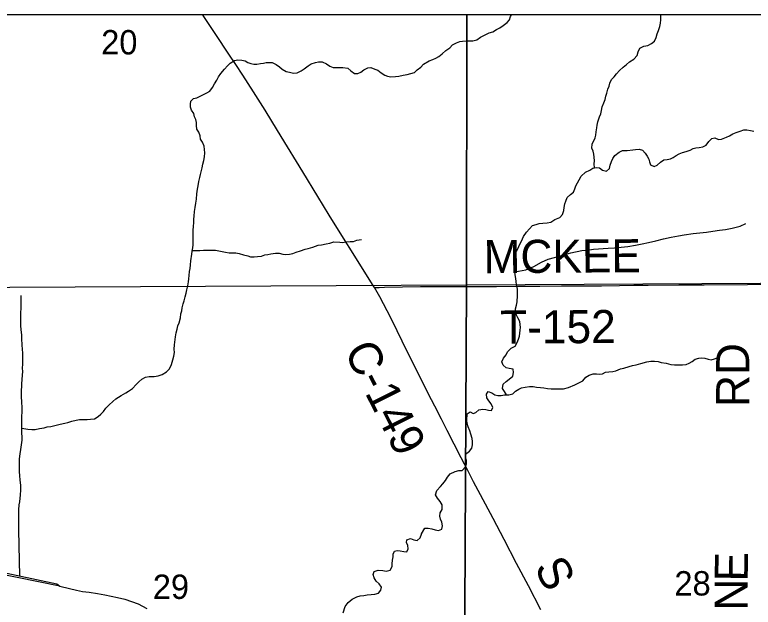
# Model space of a CAD drawing. Extents: x 0 to 34, y 0 to 22.
# Drawn here: x 4.701 to 5.97, y 19.882 to 20.9 of the extents above; entities that cross this region are included whole.
import ezdxf

# ---------------------------------------------------------------- set-up
doc = ezdxf.new("R2010")
doc.units = 0
for name, color, linetype in [('Default', 7, 'Continuous'), ('GM_X_County_Road', 7, 'Continuous'), ('GM_X_County_Road_Text', 7, 'Continuous'), ('GM_X_Minor_River', 7, 'Continuous'), ('GM_X_Section', 7, 'Continuous'), ('GM_X_Section_Text', 7, 'Continuous'), ('GM_X_Township_Road', 7, 'Continuous'), ('GM_X_Township_Road_Text', 7, 'Continuous'), ('SH_Cut_Line', 7, 'Continuous')]:
    doc.layers.add(name, color=color, linetype=linetype)

msp = doc.modelspace()

# ---------------------------------------------------------------- linework, layer by layer
at = {"layer": 'Default'}
msp.add_lwpolyline([(8.9, 20.9), (2.6032, 20.9), (2.6032, 20.8721), (2.6224, 19.9515), (2.6281, 18.8843)], dxfattribs=at)
for points in [[(5.4779, 20.9), (4.4666, 20.9), (4.4682, 20.4307), (5.4771, 20.4356)], [(6.4922, 20.9), (5.4779, 20.9), (5.4771, 20.4356), (6.4874, 20.4413)]]:
    msp.add_lwpolyline(points, close=True, dxfattribs=at)
at = {"layer": 'GM_X_County_Road'}
for points in [[(5.3193, 20.431), (5.3188, 20.4318), (5.2828, 20.4898), (5.2662, 20.5161), (5.2416, 20.5557), (5.2221, 20.5875), (5.1961, 20.6299), (5.1589, 20.6909), (5.1426, 20.7173), (5.1311, 20.7358), (5.1113, 20.7674), (5.0927, 20.7961), (5.0809, 20.8143), (5.0687, 20.8323), (5.0464, 20.866), (5.0259, 20.8971), (5.024, 20.9)], [(5.605, 19.8769), (5.5837, 19.9184), (5.5635, 19.9569), (5.5418, 19.9981), (5.5229, 20.0339), (5.5011, 20.0751), (5.4896, 20.0971), (5.4796, 20.1164), (5.4683, 20.1386), (5.4443, 20.1856), (5.4343, 20.2049), (5.4231, 20.2271), (5.4117, 20.2492), (5.3934, 20.2851), (5.3755, 20.3214), (5.3493, 20.3742), (5.3408, 20.3908), (5.3281, 20.4152), (5.3193, 20.431)]]:
    msp.add_lwpolyline(points, dxfattribs=at)
at = {"layer": 'GM_X_Minor_River'}
for points in [[(5.5345, 20.8777), (5.5402, 20.8815), (5.547, 20.8865), (5.5512, 20.8914), (5.553, 20.8971), (5.5549, 20.9)], [(5.6972, 20.6368), (5.6967, 20.6438), (5.697, 20.6488), (5.6966, 20.6552), (5.6962, 20.6602), (5.6947, 20.6655), (5.6927, 20.6704), (5.6931, 20.6776), (5.6983, 20.6883), (5.6995, 20.6932), (5.7002, 20.6986), (5.7013, 20.7054), (5.702, 20.7104), (5.7028, 20.7157), (5.7057, 20.7245), (5.708, 20.7298), (5.7091, 20.7355), (5.7106, 20.7416), (5.7132, 20.7488), (5.7155, 20.7542), (5.7169, 20.7599), (5.7184, 20.7652), (5.7203, 20.772), (5.7222, 20.7774), (5.7237, 20.7823), (5.7263, 20.7888), (5.7312, 20.7934), (5.7353, 20.7987), (5.7402, 20.8041), (5.7463, 20.8098), (5.752, 20.8144), (5.7572, 20.819), (5.7648, 20.8236), (5.7705, 20.8297), (5.772, 20.8362), (5.775, 20.8426), (5.7822, 20.8457), (5.7886, 20.8473), (5.795, 20.8503), (5.8003, 20.8545), (5.8033, 20.861), (5.8052, 20.8671), (5.8071, 20.8728), (5.8097, 20.88), (5.8104, 20.8858), (5.8111, 20.8915), (5.8111, 20.9)], [(5.0174, 20.6981), (5.014, 20.7031), (5.0136, 20.7095), (5.0135, 20.7149), (5.012, 20.7198), (5.0097, 20.7247), (5.0089, 20.73), (5.0047, 20.7361), (5.0028, 20.741), (5.0031, 20.7464), (5.0035, 20.7513), (5.0084, 20.7563), (5.0137, 20.7574), (5.0198, 20.7598), (5.0254, 20.7628), (5.0311, 20.7655), (5.036, 20.7686), (5.0409, 20.7747), (5.0443, 20.7815), (5.0481, 20.7876), (5.0511, 20.7934), (5.0552, 20.7991), (5.0616, 20.8063), (5.0669, 20.8121), (5.0711, 20.817), (5.0786, 20.8216), (5.0843, 20.8224), (5.0912, 20.8217), (5.0969, 20.8206), (5.1018, 20.8179), (5.1067, 20.816), (5.1121, 20.8149), (5.117, 20.8153), (5.1231, 20.8161), (5.1284, 20.8169), (5.1333, 20.8177), (5.1382, 20.8177), (5.1436, 20.8181), (5.15, 20.8147), (5.1557, 20.8102), (5.1607, 20.8064), (5.1672, 20.8026), (5.1729, 20.8011), (5.1801, 20.7996), (5.1865, 20.8004), (5.193, 20.8035), (5.1983, 20.8073), (5.2054, 20.8123), (5.2104, 20.8154), (5.2179, 20.8181), (5.2232, 20.8192), (5.2293, 20.8193), (5.2365, 20.8155), (5.2423, 20.8117), (5.248, 20.8095), (5.2529, 20.8091), (5.2601, 20.8091), (5.265, 20.8095), (5.2734, 20.8081), (5.2787, 20.8035), (5.2848, 20.799), (5.2905, 20.799), (5.2958, 20.8013), (5.3011, 20.8051), (5.3076, 20.809), (5.3129, 20.8094), (5.3197, 20.8067), (5.325, 20.8045), (5.3307, 20.8003), (5.3368, 20.7962), (5.3418, 20.7943), (5.3475, 20.7932), (5.3551, 20.794), (5.3608, 20.7944), (5.3683, 20.7959), (5.3755, 20.7971), (5.3816, 20.799), (5.3877, 20.801), (5.3926, 20.8052), (5.3986, 20.8101), (5.4035, 20.8151), (5.413, 20.8209), (5.4194, 20.8232), (5.4244, 20.8251), (5.43, 20.8285), (5.4357, 20.8327), (5.4417, 20.8385), (5.4489, 20.8434), (5.4531, 20.8484), (5.4599, 20.8519), (5.4656, 20.8542), (5.4705, 20.8546), (5.4781, 20.8554), (5.4883, 20.8554), (5.4952, 20.857), (5.5016, 20.8616), (5.5073, 20.8642), (5.516, 20.8688), (5.5228, 20.8708), (5.5289, 20.8746), (5.5345, 20.8777)], [(4.7131, 20.1892), (4.7233, 20.1877), (4.7302, 20.187), (4.7362, 20.187), (4.7438, 20.1889), (4.7518, 20.1901), (4.7567, 20.1916), (4.7632, 20.1924), (4.77, 20.194), (4.7791, 20.1963), (4.787, 20.1979), (4.7923, 20.1994), (4.7992, 20.2013), (4.8067, 20.2033), (4.8124, 20.2041), (4.8189, 20.2045), (4.8253, 20.2045), (4.831, 20.2049), (4.8382, 20.2057), (4.8443, 20.2092), (4.8492, 20.2134), (4.8533, 20.2183), (4.8575, 20.224), (4.8635, 20.2298), (4.8696, 20.2351), (4.8745, 20.2397), (4.8839, 20.2458), (4.8919, 20.2501), (4.8968, 20.2531), (4.9032, 20.2577), (4.9097, 20.2642), (4.9142, 20.2692), (4.9195, 20.2734), (4.9259, 20.2768), (4.932, 20.278), (4.9407, 20.278), (4.9475, 20.2792), (4.9543, 20.2819), (4.9619, 20.2865), (4.9668, 20.2915), (4.9702, 20.2987), (4.9728, 20.3067), (4.9747, 20.3132), (4.9754, 20.3196), (4.975, 20.325), (4.9753, 20.3329), (4.9772, 20.3463), (4.9786, 20.3531), (4.9801, 20.3596), (4.9812, 20.3653), (4.9835, 20.3706), (4.9857, 20.379), (4.9864, 20.3858), (4.9879, 20.3908), (4.989, 20.3961), (4.9905, 20.4034), (4.9924, 20.4083), (4.9939, 20.4152), (4.9954, 20.4212), (4.9968, 20.4273), (4.9983, 20.4338), (4.9994, 20.441), (5.0002, 20.446), (5.0009, 20.4521), (5.0016, 20.4585), (5.0023, 20.4639), (5.0031, 20.47), (5.0038, 20.4768), (5.0052, 20.4882), (5.006, 20.4935), (5.0071, 20.4996), (5.0074, 20.5046), (5.0074, 20.5103), (5.0078, 20.5156), (5.0077, 20.5293), (5.0084, 20.5365), (5.0088, 20.5426), (5.0087, 20.5487), (5.0091, 20.554), (5.0102, 20.5616), (5.0113, 20.5685), (5.0124, 20.5761), (5.0135, 20.5829), (5.0138, 20.5924), (5.0149, 20.6004), (5.016, 20.6061), (5.0175, 20.6134), (5.019, 20.6202), (5.0201, 20.6252), (5.0216, 20.6301), (5.0231, 20.637), (5.0245, 20.6434), (5.026, 20.6495), (5.0271, 20.656), (5.0275, 20.6625), (5.0271, 20.6685), (5.0263, 20.6739), (5.0236, 20.6811), (5.0201, 20.6864), (5.0194, 20.6921), (5.0174, 20.6981)], [(5.8325, 20.6547), (5.8374, 20.6581), (5.8427, 20.6612), (5.8484, 20.6635), (5.8548, 20.6651), (5.8617, 20.6674), (5.8666, 20.67), (5.8715, 20.6712), (5.8772, 20.672), (5.8833, 20.6732), (5.8893, 20.6758), (5.8938, 20.682), (5.8991, 20.6873), (5.9041, 20.6885), (5.9105, 20.6858), (5.9155, 20.6859), (5.9242, 20.6893), (5.9291, 20.6916), (5.9351, 20.6951), (5.9408, 20.6978), (5.9473, 20.6997), (5.9537, 20.702), (5.959, 20.702), (5.9651, 20.7013), (5.9712, 20.6998)], [(5.5462, 20.2466), (5.5428, 20.2523), (5.5393, 20.2576), (5.5404, 20.2648), (5.5453, 20.2694), (5.5506, 20.2736), (5.5567, 20.2789), (5.5581, 20.285), (5.5574, 20.2907), (5.5505, 20.2918), (5.5456, 20.293), (5.5402, 20.2979), (5.5379, 20.3036), (5.5409, 20.3097), (5.5455, 20.3154), (5.5477, 20.3207), (5.5541, 20.3268), (5.5609, 20.3303), (5.5643, 20.3364), (5.5669, 20.3425), (5.5681, 20.3478), (5.5695, 20.3577), (5.5699, 20.3626), (5.5695, 20.3676), (5.5687, 20.3725), (5.5656, 20.379), (5.5633, 20.3839), (5.5618, 20.3888), (5.5617, 20.3945), (5.5632, 20.401), (5.5643, 20.4067), (5.565, 20.4174), (5.565, 20.4284), (5.5634, 20.4356), (5.5626, 20.4417), (5.5618, 20.4466), (5.5611, 20.4531), (5.5606, 20.458), (5.5595, 20.4634), (5.5602, 20.4691), (5.5606, 20.4744), (5.5616, 20.4866), (5.5631, 20.4938), (5.5661, 20.4987), (5.5684, 20.5045), (5.5718, 20.5109), (5.5751, 20.5189), (5.5804, 20.5262), (5.5853, 20.5323), (5.5906, 20.5376), (5.597, 20.5396), (5.6023, 20.5411), (5.6084, 20.5415), (5.616, 20.5423), (5.6224, 20.5435), (5.6292, 20.5481), (5.6376, 20.5515), (5.6425, 20.5569), (5.6443, 20.5634), (5.6451, 20.5687), (5.6462, 20.5748), (5.6477, 20.5797), (5.6503, 20.5858), (5.656, 20.5908), (5.6609, 20.595), (5.6635, 20.6007), (5.6654, 20.606), (5.668, 20.611), (5.671, 20.6163), (5.6744, 20.6224), (5.6816, 20.6293), (5.6895, 20.6328), (5.6944, 20.6362), (5.7001, 20.6374), (5.7058, 20.6366), (5.7112, 20.6328), (5.718, 20.631), (5.7229, 20.6359), (5.724, 20.6413), (5.7266, 20.6477), (5.7285, 20.6527), (5.7323, 20.658), (5.7395, 20.6638), (5.7455, 20.6665), (5.7531, 20.6669), (5.763, 20.6677), (5.7679, 20.6685), (5.774, 20.6689), (5.7797, 20.667), (5.7843, 20.6621), (5.7877, 20.6568), (5.7908, 20.6518), (5.7919, 20.6469), (5.7935, 20.642), (5.7999, 20.6393), (5.8049, 20.6413), (5.8109, 20.6466), (5.8162, 20.6504), (5.8223, 20.6512), (5.8276, 20.6524), (5.8325, 20.6547)], [(5.5606, 20.458), (5.5792, 20.4614), (5.5928, 20.4675), (5.6063, 20.4748), (5.6177, 20.4798), (5.6286, 20.4829), (5.6566, 20.4907), (5.6752, 20.4946), (5.685, 20.4954), (5.6956, 20.497), (5.7206, 20.4986), (5.7316, 20.4994), (5.7429, 20.5007), (5.7543, 20.5019), (5.7679, 20.5038), (5.7789, 20.5062), (5.7902, 20.5085), (5.8027, 20.5116), (5.816, 20.5147), (5.8292, 20.5175), (5.8417, 20.5198), (5.8515, 20.5218), (5.867, 20.5241), (5.8898, 20.5265), (5.9007, 20.5281), (5.9121, 20.5297), (5.9223, 20.5309), (5.9337, 20.5329), (5.9477, 20.5367), (5.9575, 20.541)], [(5.0062, 20.4949), (5.0193, 20.4947), (5.0253, 20.4951), (5.0341, 20.4952), (5.0409, 20.4956), (5.0462, 20.4956), (5.0633, 20.4919), (5.0697, 20.4908), (5.0811, 20.4905), (5.0865, 20.4897), (5.0941, 20.4875), (5.1013, 20.4856), (5.1062, 20.4837), (5.1127, 20.4838), (5.1184, 20.4842), (5.1248, 20.4853), (5.1309, 20.4873), (5.1358, 20.4877), (5.1411, 20.4888), (5.1491, 20.49), (5.1555, 20.4904), (5.1616, 20.4885), (5.1665, 20.4878), (5.1734, 20.4882), (5.1791, 20.4898), (5.1847, 20.4917), (5.1919, 20.494), (5.1999, 20.4971), (5.2052, 20.4982), (5.2135, 20.5006), (5.2226, 20.5037), (5.2279, 20.5044), (5.2359, 20.506), (5.2427, 20.5072), (5.2492, 20.5099), (5.2598, 20.5091), (5.2647, 20.5088), (5.27, 20.5096), (5.2772, 20.5104), (5.2829, 20.51), (5.289, 20.5127), (5.297, 20.5135)], [(4.7099, 19.9355), (4.7079, 20.0142), (4.7078, 20.0428), (4.7081, 20.0488), (4.7088, 20.0576), (4.7096, 20.0629), (4.711, 20.0751), (4.7117, 20.0831), (4.7113, 20.0914), (4.7101, 20.0998), (4.7097, 20.1078), (4.7093, 20.1142), (4.7092, 20.1367), (4.7103, 20.1451), (4.7114, 20.153), (4.7125, 20.1606), (4.7136, 20.1686), (4.7139, 20.1736), (4.7131, 20.1819), (4.713, 20.1991), (4.7134, 20.2044), (4.7134, 20.2097), (4.7137, 20.2173), (4.7136, 20.2257), (4.7132, 20.2333), (4.7124, 20.2447), (4.7124, 20.2496), (4.7127, 20.2546), (4.7131, 20.261), (4.7134, 20.266), (4.7138, 20.2724), (4.7145, 20.2808), (4.7148, 20.2861), (4.7144, 20.2934), (4.7148, 20.2991), (4.7151, 20.3067), (4.7151, 20.312), (4.7147, 20.3188), (4.7146, 20.3249), (4.7138, 20.3329), (4.7134, 20.3428), (4.713, 20.35), (4.7122, 20.3584), (4.7118, 20.366), (4.7114, 20.3717), (4.7113, 20.3774), (4.7117, 20.3827), (4.7113, 20.3884), (4.712, 20.3949), (4.712, 20.4006), (4.7123, 20.4063), (4.7123, 20.412), (4.7119, 20.4177)], [(5.4001, 20.0077), (5.4058, 20.0178), (5.4112, 20.0175), (5.4176, 20.0163), (5.4237, 20.0145), (5.4294, 20.0137), (5.4347, 20.016), (5.4362, 20.0217), (5.435, 20.0278), (5.4327, 20.0331), (5.4312, 20.0381), (5.4319, 20.0438), (5.4357, 20.0499), (5.4356, 20.0579), (5.4318, 20.0636), (5.4276, 20.0692), (5.4241, 20.0749), (5.4264, 20.0825), (5.4324, 20.089), (5.4369, 20.094), (5.4411, 20.0993), (5.4445, 20.1054), (5.4494, 20.1112), (5.4577, 20.115), (5.4641, 20.1169), (5.4698, 20.1166), (5.4755, 20.1227), (5.4774, 20.128), (5.4773, 20.1337), (5.4758, 20.1394), (5.4758, 20.1447), (5.4822, 20.1501), (5.4867, 20.1551), (5.4874, 20.1608), (5.4874, 20.1665), (5.487, 20.1714), (5.4847, 20.179), (5.4828, 20.1851), (5.4801, 20.1915), (5.4785, 20.1972), (5.4777, 20.2025), (5.4784, 20.2139), (5.4837, 20.2174), (5.4887, 20.2148), (5.4936, 20.2163), (5.4985, 20.2209), (5.5053, 20.2221), (5.5103, 20.2213), (5.5152, 20.2202), (5.5205, 20.2198), (5.5224, 20.2248), (5.5197, 20.2312), (5.5155, 20.2362), (5.5124, 20.2415), (5.5117, 20.2476), (5.5147, 20.2525), (5.5207, 20.2503), (5.5261, 20.2469), (5.5314, 20.2454), (5.5371, 20.2458), (5.5424, 20.2466), (5.55, 20.2466), (5.5568, 20.2485), (5.5617, 20.2531), (5.567, 20.2562), (5.5719, 20.2585), (5.578, 20.2596), (5.5856, 20.2612), (5.5917, 20.2612), (5.5977, 20.2597), (5.6046, 20.2594), (5.6099, 20.2586), (5.6164, 20.2575), (5.6228, 20.2572), (5.6285, 20.2572), (5.6353, 20.2572), (5.6441, 20.2569), (5.6528, 20.2592), (5.6634, 20.2638), (5.6717, 20.2677), (5.677, 20.2707), (5.6823, 20.2768), (5.688, 20.2807), (5.6948, 20.2826), (5.7005, 20.2826), (5.7062, 20.2823), (5.7111, 20.2827), (5.7164, 20.2854), (5.7221, 20.2865), (5.7285, 20.2869), (5.7338, 20.2881), (5.7422, 20.2912), (5.7475, 20.2927), (5.757, 20.2954), (5.7626, 20.297), (5.7691, 20.2985), (5.7767, 20.3008), (5.7873, 20.3035), (5.7941, 20.3043), (5.8006, 20.3044), (5.8066, 20.304)], [(5.8066, 20.304), (5.812, 20.3025), (5.8203, 20.3014), (5.8283, 20.2988), (5.8348, 20.2981), (5.8404, 20.2981), (5.8484, 20.2985), (5.8549, 20.2989), (5.8598, 20.3012), (5.8651, 20.3039), (5.87, 20.3081), (5.8764, 20.3096), (5.8818, 20.3101), (5.8867, 20.3097), (5.8928, 20.3082), (5.8977, 20.3071), (5.9034, 20.3086), (5.9083, 20.3102)], [(4.7786, 19.9178), (4.3381, 20.0075)], [(4.3616, 20.0095), (4.7733, 19.922)], [(5.2651, 19.8723), (5.2689, 19.883), (5.2742, 19.8898), (5.2811, 19.8955), (5.2887, 19.8997), (5.2944, 19.9012), (5.3009, 19.902), (5.3067, 19.9027), (5.3135, 19.9035), (5.32, 19.9042), (5.3261, 19.9057), (5.3303, 19.9107), (5.3311, 19.916), (5.3272, 19.9217), (5.3219, 19.9267), (5.3184, 19.9324), (5.3169, 19.9377), (5.3184, 19.943), (5.3256, 19.9453), (5.3333, 19.9449), (5.3394, 19.9434), (5.3462, 19.9453), (5.3497, 19.9514), (5.3497, 19.9563), (5.3504, 19.9628), (5.3512, 19.9681), (5.3515, 19.973), (5.3534, 19.978), (5.3584, 19.9791), (5.3633, 19.9787), (5.3698, 19.9772), (5.3748, 19.9768), (5.3771, 19.9818), (5.3767, 19.9879), (5.3744, 19.9928), (5.3747, 19.9977), (5.3809, 19.9996), (5.387, 19.9974), (5.3923, 19.9966), (5.3976, 20.0012), (5.3999, 20.0072), (5.4001, 20.0077)], [(4.7733, 19.922), (4.7786, 19.9178)], [(4.7786, 19.9178), (4.7949, 19.9141), (4.8074, 19.9111), (4.8177, 19.9089), (4.829, 19.9074), (4.8431, 19.9055), (4.8559, 19.9029), (4.8666, 19.9007), (4.8776, 19.8984), (4.8901, 19.8955), (4.9014, 19.8913), (4.9132, 19.8872), (4.928, 19.8793)]]:
    msp.add_lwpolyline(points, dxfattribs=at)
at = {"layer": 'GM_X_Section'}
for points in [[(4.4682, 20.4307), (5.4771, 20.4356), (5.472, 19.4291), (4.4662, 19.4189)], [(5.4771, 20.4356), (6.4874, 20.4413), (6.4824, 19.4291), (5.472, 19.4291)]]:
    msp.add_lwpolyline(points, close=True, dxfattribs=at)
at = {"layer": 'GM_X_Township_Road'}
msp.add_lwpolyline([(5.3193, 20.431), (5.324, 20.4312), (5.3271, 20.4314), (5.3363, 20.4318), (5.3673, 20.4324), (5.3983, 20.4327), (5.4139, 20.433), (5.4294, 20.4331), (5.4946, 20.4328), (5.5288, 20.4329), (5.563, 20.4332), (5.6034, 20.4334), (5.6407, 20.4339), (5.6748, 20.4342), (5.709, 20.4343), (5.74, 20.4346), (5.7648, 20.435), (5.7896, 20.4354), (5.8424, 20.4359), (5.8859, 20.436), (5.9604, 20.4366), (5.9853, 20.4367), (5.9863, 20.4368)], dxfattribs=at)
at = {"layer": 'SH_Cut_Line'}
msp.add_lwpolyline([(8.9, 20.9), (2.6032, 20.9), (2.6032, 20.8721), (2.6224, 19.9515), (2.6281, 18.8843), (2.6292, 18.3794), (2.6263, 18.3795), (2.6204, 18.3797), (2.6161, 18.3799), (2.6118, 18.3803), (2.6122, 18.05), (2.6129, 17.8818), (2.6231, 17.3771), (2.6332, 16.3685)], dxfattribs=at)

# ---------------------------------------------------------------- texts
at = {"layer": 'GM_X_County_Road_Text'}
for s, height, rotation, p in [('C-149', 0.05682, 296.6939, (5.2661, 20.3221)), ('S', 0.0568, 297.1221, (5.5928, 19.9502))]:
    msp.add_text(s, height=height, rotation=rotation, dxfattribs=at).set_placement(p)
at = {"layer": 'GM_X_Section_Text'}
for s, p in [('20', (4.8496, 20.8318)), ('29', (4.9383, 19.8959)), ('28', (5.8346, 19.9018))]:
    msp.add_text(s, height=0.04186, rotation=0, dxfattribs=at).set_placement(p)
at = {"layer": 'GM_X_Township_Road_Text'}
for s, height, rotation, p in [('MCKEE', 0.05682, 0.3927, (5.5069, 20.4557)), ('T-152', 0.05682, 0.2793, (5.5353, 20.3348)), ('RD', 0.05682, 90, (5.9631, 20.2259)), ('E', 0.0568, 89.3271, (5.9605, 19.9256)), ('N', 0.0568, 89.8488, (5.9604, 19.8757))]:
    msp.add_text(s, height=height, rotation=rotation, dxfattribs=at).set_placement(p)

doc.saveas('drawing.dxf')
